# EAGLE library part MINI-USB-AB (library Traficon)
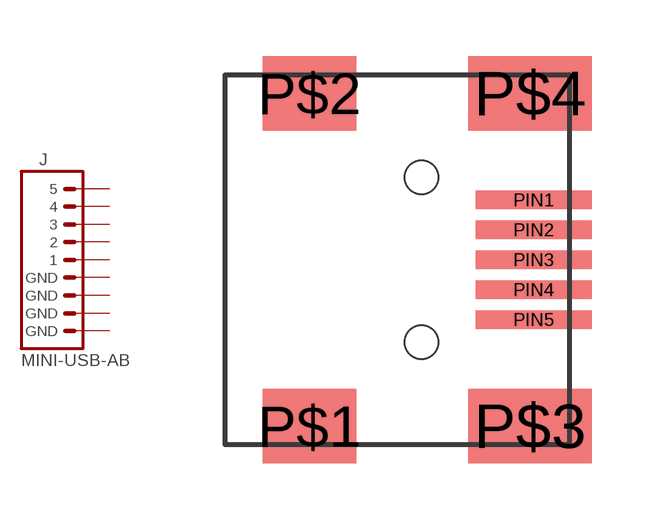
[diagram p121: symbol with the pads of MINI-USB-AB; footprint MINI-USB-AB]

Designator prefix J

## MINI-USB-AB  [MINI-USB-AB]
P$1  GND  pas
P$2  GND  pas
P$3  GND  pas
P$4  GND  pas
PIN1  1  pas
PIN2  2  pas
PIN3  3  pas
PIN4  4  pas
PIN5  5  pas

## Footprint MINI-USB-AB (pad centres in mm)
smd 2.5 x 2: P$1 2.25,-4.45; P$2 2.25,4.45
smd 3.3 x 2: P$3 8.15,-4.45; P$4 8.15,4.45
smd 3.1 x 0.5: PIN1 8.25,1.6; PIN2 8.25,0.8; PIN3 8.25,0; PIN4 8.25,-0.8; PIN5 8.25,-1.6
hole 0.9 at 5.25,-2.2
hole 0.9 at 5.25,2.2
